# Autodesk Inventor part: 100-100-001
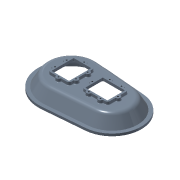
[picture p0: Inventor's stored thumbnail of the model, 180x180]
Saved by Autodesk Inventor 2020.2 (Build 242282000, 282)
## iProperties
Created: 2010-02
Part Number: 100-100-001
Document SubType Name: Modeling
Designer: F.Stasiak
Density: 7.15 g/cm^3
Material: Żeliwo szare
Mass: 38811.4 g
Surface Area: 10852.3 cm^2
Volume: 5428.17 cm^3
Appearance: Stalowoniebieska
Manager: www.cadconsulting.pl
Company: Fabian Stasiak CAD Consulting
Author: F.Stasiak
Subject: Zbiór ćwiczeń. Autodesk Inventor 2020. Kurs podstawowy
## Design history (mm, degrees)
sketch "Szkic1"
  geometry: L1 (-153.571, -249.08)-(193.857, -219.19); L2 (193.857, 219.19)-(-153.571, 249.08); L3 (-175, 0)-(175, 0); A1 r 220 centre (175, 0) between (193.857, -219.19) and (193.857, 219.19); A2 r 250 centre (-175, 0) between (-153.571, 249.08) and (-153.571, -249.08); 2 further points
  constraints: 6 end point, 4 point on circle, 4 tangent, 2 centre point, 2 coincident, 1 horizontal, 1 midpoint
  dimensions: "d0" = 350 distance of L3.end A2.centre; "d1" = 250 radius of A2; "d2" = 220 radius of A1
extrude "Wyciągnięcie proste1" new body sketch "Szkic1" distance "d3" = 100; taper "d4" = -30 deg
fillet "Zaokrąglenie1" dims "d5" = 40
sketch "Szkic2"
  geometry: L1 (153.571, -249.08)-(-193.857, -219.19) reference; L2 (-193.857, 219.19)-(153.571, 249.08) reference; L3 (-196.429, -249.08)-(151, -278.97); L4 (151, 278.97)-(-196.429, 249.08); A1 r 250 centre (175, 0) between (153.571, -249.08) and (153.571, 249.08) reference; A2 r 220 centre (-175, 0) between (-193.857, 219.19) and (-193.857, -219.19) reference; A3 r 280 centre (175, 0) between (151, -278.97) and (151, 278.97); A4 r 250 centre (-175, 0) between (-196.429, 249.08) and (-196.429, -249.08); 1 further point
  constraints: 4 end point, 4 point on circle, 2 centre point, 3 other
  dimensions: "d6" = 30 radial gap between concentric circles of A4 A2
extrude "Wyciągnięcie proste2" join sketch "Szkic2" distance "d7" = 20; taper "d8" = 0 deg
feature "Skorupa1" dims "d18" = 8, "d19" = 40
sketch "Szkic3"
  geometry: L1 (-265, -90)-(-265, 90); L2 (-245, 110)-(-105, 110); L3 (-85, 90)-(-85, -90); L4 (-105, -110)-(-245, -110); L5 (-265, 50)-(-85, 50); L6 (-265, -50)-(-85, -50); L7 (-175, 50)-(-175, -50); L8 (-105, 95)-(-245, 95); L9 (-250, 90)-(-250, -90); L10 (-245, -95)-(-105, -95); L11 (-100, -90)-(-100, 90); C1 r 20 at (-175, 110); C2 r 20 at (-175, -110); C3 r 20 at (-265, -50); C4 r 20 at (-265, 50); C5 r 20 at (-85, 50); C6 r 20 at (-85, -50); A1 r 169.171 centre (-175, 0) between (-160.5, 168.548) and (-160.5, -168.548) reference; A2 r 20 centre (-245, 90) between (-245, 110) and (-265, 90); A3 r 20 centre (-105, 90) between (-85, 90) and (-105, 110); A4 r 20 centre (-105, -90) between (-105, -110) and (-85, -90); A5 r 20 centre (-245, -90) between (-265, -90) and (-245, -110); A6 r 5 centre (-245, 90) between (-245, 95) and (-250, 90); A7 r 5 centre (-245, -90) between (-250, -90) and (-245, -95); A8 r 5 centre (-105, -90) between (-105, -95) and (-100, -90); A9 r 5 centre (-105, 90) between (-100, 90) and (-105, 95); 4 further points
  constraints: 22 end point, 16 point on circle, 14 centre point, 8 equal radius, 8 tangent, 6 midpoint, 4 parallel, 4 point on line, 2 coincident, 2 perpendicular, 1 horizontal, 1 horizontal alignment, 1 vertical, 1 vertical alignment, 7 other
  dimensions: "d10" = 20 radius of A2; "d11" = 180 distance between parallel lines of L1 L3; "d12" = 220 distance between parallel lines of L2 L4; "d20" = 40 diameter of C1; "d21" = 100 distance of L5.end L6.end; "d31" = 15 distance between parallel lines of L3 L11
extrude "Wyciągnięcie proste3" join sketch "Szkic3" distance "d16" = 25; taper "d17" = 0 deg
extrude "Wyciągnięcie proste4" cut sketch "Szkic3" extent not by distance; stored distance "d33" = 5; taper "d34" = 0 deg
sketch "Szkic4"
  geometry: A1 r 20 centre (-265, 50) between (-265, 70) and (-265, 30) reference; A2 r 20 centre (-265, -50) between (-265, -30) and (-265, -70) reference; A3 r 20 centre (-175, -110) between (-195, -110) and (-155, -110) reference; A4 r 20 centre (-85, -50) between (-85, -70) and (-85, -30) reference; A5 r 20 centre (-85, 50) between (-85, 30) and (-85, 70) reference; A6 r 20 centre (-175, 110) between (-155, 110) and (-195, 110) reference; 1 further point
hole "Otwory1" sketch "Szkic4" at (-175, 110), (-85, 50), (-85, -50), (-175, -110), (-265, -50), (-265, 50) diameter "d36" = 11.835; stored, may be unused: countersink angle "d40" = 90 deg, drill point angle "d42" = 118 deg; dims "d37" = 15, "d38" = 4, "d39" = 2, "d41" = 25
fillet "Zaokrąglenie3" dims "d43" = 5
fillet "Zaokrąglenie4" dims "d44" = 5
sketch "Szkic5"
  geometry: L1 (-258.872, -83.376)-(-258.872, 96.624); L2 (-238.872, 116.624)-(-98.872, 116.624); L3 (-78.872, 96.624)-(-78.872, -83.376); L4 (-98.872, -103.376)-(-238.872, -103.376); L5 (-258.872, 56.624)-(-78.872, 56.624); L6 (-258.872, -43.376)-(-78.872, -43.376); L7 (-168.872, 56.624)-(-168.872, -43.376); L8 (-98.872, 101.624)-(-238.872, 101.624); L9 (-243.872, 96.624)-(-243.872, -83.376); L10 (-238.872, -88.376)-(-98.872, -88.376); L11 (-93.872, -83.376)-(-93.872, 96.624); L12 (-243.367, -188.376)-(-258.872, -188.376) reference; C1 r 20 at (-168.872, 116.624); C2 r 20 at (-168.872, -103.376); C3 r 20 at (-258.872, -43.376); C4 r 20 at (-258.872, 56.624); C5 r 20 at (-78.872, 56.624); C6 r 20 at (-78.872, -43.376); A1 r 20 centre (-238.872, 96.624) between (-238.872, 116.624) and (-258.872, 96.624); A2 r 20 centre (-98.872, 96.624) between (-78.872, 96.624) and (-98.872, 116.624); A3 r 20 centre (-98.872, -83.376) between (-98.872, -103.376) and (-78.872, -83.376); A4 r 20 centre (-238.872, -83.376) between (-258.872, -83.376) and (-238.872, -103.376); A5 r 5 centre (-238.872, 96.624) between (-238.872, 101.624) and (-243.872, 96.624); A6 r 5 centre (-238.872, -83.376) between (-243.872, -83.376) and (-238.872, -88.376); A7 r 5 centre (-98.872, -83.376) between (-98.872, -88.376) and (-93.872, -83.376); A8 r 5 centre (-98.872, 96.624) between (-93.872, 96.624) and (-98.872, 101.624); A9 r 139.171 centre (-168.872, 66.624) between (-30.213, 78.553) and (-307.531, 78.553) reference; A10 r 25 centre (-218.872, -193.376) between (-194.377, -188.376) and (-243.367, -188.376) reference; 4 further points
  constraints: 22 end point, 16 point on circle, 14 centre point, 9 tangent, 8 equal radius, 6 midpoint, 5 parallel, 4 point on line, 2 perpendicular, 1 coincident, 1 horizontal, 1 vertical, 7 other
  dimensions: "d50" = 20 radius of A1; "d49" = 180 distance between parallel lines of L1 L3; "d48" = 220 distance between parallel lines of L2 L4; "d47" = 40 diameter of C1; "d46" = 100 distance of L5.end L6.end; "d45" = 15 distance between parallel lines of L3 L11; "d67" = 60 distance of point (-168.872, 6.624) A9.centre
extrude "Wyciągnięcie proste5" join sketch "Szkic5" taper "d52" = 0 deg; distance "d53" = 25
extrude "Wyciągnięcie proste6" cut sketch "Szkic5" extent not by distance; taper "d55" = 0 deg; stored distance "d56" = 5
sketch "Szkic6"
  geometry: A1 r 20 centre (-258.872, 56.624) between (-258.872, 76.624) and (-258.872, 36.624) reference; A2 r 20 centre (-258.872, -43.376) between (-258.872, -23.376) and (-258.872, -63.376) reference; A3 r 20 centre (-168.872, -103.376) between (-188.872, -103.376) and (-148.872, -103.376) reference; A4 r 20 centre (-78.872, -43.376) between (-78.872, -63.376) and (-78.872, -23.376) reference; A5 r 20 centre (-78.872, 56.624) between (-78.872, 36.624) and (-78.872, 76.624) reference; A6 r 20 centre (-168.872, 116.624) between (-148.872, 116.624) and (-188.872, 116.624) reference; 1 further point
hole "Otwory2" sketch "Szkic6" at (-168.872, 116.624), (-78.872, 56.624), (-78.872, -43.376), (-168.872, -103.376), (-258.872, -43.376), (-258.872, 56.624) diameter "d63" = 11.835; stored, may be unused: drill point angle "d58" = 118 deg, countersink angle "d59" = 90 deg; dims "d57" = 15, "d60" = 2, "d61" = 4, "d62" = 25
fillet "Zaokrąglenie5" dims "d64" = 5
fillet "Zaokrąglenie6" dims "d65" = 5
chamfer "Faza1" distance "d71" = 10; stored, may be unused: second distance "d72" = 2, angle "d73" = 45 deg
node "Bryła1"
other parameters: "d88" = 0, "d89" = 0, "d90" = 0, "d91" = 0, "d92" = 0, "d93" = 0
